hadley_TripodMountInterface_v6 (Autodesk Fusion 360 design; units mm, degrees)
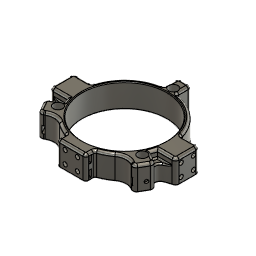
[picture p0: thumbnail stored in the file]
base_mesh_feature "Base Mesh Feature1"
base_mesh_feature "Base Mesh Feature2"
modify "Modify1"
sketch "Sketch2" plane through (0, 0, 0) normal (0, 1, 0) x axis (1, 0, 0)
  line L1 (-90, -12) -> (-90, 12)
  line L2 (90, 12) -> (90, -12)
  line L3 (66.5601, 17) -> (85, 17)
  line L4 (-5, 86.0607) -> (5, 86.0607)
  line L5 (-9, 68.4562) -> (-9, 82.0607)
  line L6 (76.5308, -39.5663) -> (69.8712, -51.101)
  line L7 (61.6032, -52.1011) -> (63.041, -52.9312)
  line L8 (0, 100) -> (0, -90)
  line L9 (-61.5608, -25.1499) -> (-74.7006, -32.7361)
  line L10 (-76.5308, -39.5663) -> (-69.8712, -51.101)
  line L11 (-61.6032, -52.1011) -> (-63.041, -52.9312)
  line L12 (-16.625, -76.125) -> (16.625, -76.125)
  line L13 (85, -17) -> (64.2904, -17)
  line L14 (61.5608, -25.1499) -> (74.7006, -32.7361)
  line L15 (20.625, -56.8758) -> (20.625, -56.875)
  line L16 (20.625, -72.125) -> (20.625, -65.3614)
  line L17 (-20.625, -65.3614) -> (-20.625, -72.125)
  line L18 (-20.625, -56.875) -> (-20.625, -56.8758)
  line L19 (-64.2904, -17) -> (-85, -17)
  line L20 (-85, 17) -> (-66.5601, 17)
  line L21 (9, 82.0607) -> (9, 68.4562)
  curve K1 (74.7006, -32.7361) -> (85, -17)
  curve K2 (81.4412, -18.2716) -> (88.5588, -15.7284)
  curve K3 (-74.7006, -32.7361) -> (-85, -17)
  curve K4 (77.6528, -34.2592) -> (71.7485, -31.2131)
  curve K5 (-81.4412, -18.2716) -> (-88.5588, -15.7284)
  curve K6 (-77.6528, -34.2592) -> (-71.7485, -31.2131)
  circle C1 centre (0, 0) radius 60.5
  circle C2 centre (-0.0046, 69.7633) radius 6.7
  circle C3 centre (-60.4144, -34.8856) radius 6.7
  circle C4 centre (60.4191, -34.8776) radius 6.7
  arc A1 centre (0, 0) radius 66.5 clockwise from (64.2904, -17) to (61.5608, -25.1499)
  arc A2 centre (0, 0) radius 66.5 clockwise from (39.6719, -53.3703) to (22.6052, -62.54)
  arc A3 centre (0, 0) radius 66.5 clockwise from (-22.6052, -62.54) to (-39.6719, -53.3703)
  arc A4 centre (0, 0) radius 66.5 clockwise from (-61.5608, -25.1499) to (-64.2904, -17)
  arc A5 centre (0, 0) radius 66.5 clockwise from (-63.687, 19.1367) to (-11.482, 65.5012)
  arc A6 centre (0, 0) radius 66.5 clockwise from (11.482, 65.5012) to (63.687, 19.1367)
  arc A7 centre (51.6032, -69.4216) radius 20 clockwise from (39.6719, -53.3703) to (61.6032, -52.1011)
  arc A8 centre (-51.6032, -69.4216) radius 20 clockwise from (-61.6032, -52.1011) to (-39.6719, -53.3703)
  arc A9 centre (66.5601, 20) radius 3 clockwise from (66.5601, 17) to (63.687, 19.1367)
  arc A10 centre (12, 68.4562) radius 3 clockwise from (11.482, 65.5012) to (9, 68.4562)
  arc A11 centre (-12, 68.4562) radius 3 clockwise from (-9, 68.4562) to (-11.482, 65.5012)
  arc A12 centre (-66.5601, 20) radius 3 clockwise from (-63.687, 19.1367) to (-66.5601, 17)
  arc A13 centre (23.625, -65.3614) radius 3 clockwise from (20.625, -65.3614) to (22.6052, -62.54)
  arc A14 centre (-23.625, -65.3614) radius 3 clockwise from (-22.6052, -62.54) to (-20.625, -65.3614)
  arc A15 centre (85, 12) radius 5 clockwise from (85, 17) to (90, 12)
  arc A16 centre (85, -12) radius 5 clockwise from (90, -12) to (85, -17)
  arc A17 centre (72.2006, -37.0663) radius 5 clockwise from (74.7006, -32.7361) to (76.5308, -39.5663)
  arc A18 centre (65.541, -48.601) radius 5 clockwise from (69.8712, -51.101) to (63.041, -52.9312)
  arc A19 centre (-65.541, -48.601) radius 5 clockwise from (-63.041, -52.9312) to (-69.8712, -51.101)
  arc A20 centre (-72.2006, -37.0663) radius 5 clockwise from (-76.5308, -39.5663) to (-74.7006, -32.7361)
  arc A21 centre (-85, -12) radius 5 clockwise from (-85, -17) to (-90, -12)
  arc A22 centre (-85, 12) radius 5 clockwise from (-90, 12) to (-85, 17)
  arc A23 centre (16.625, -72.125) radius 4 clockwise from (20.625, -72.125) to (16.625, -76.125)
  arc A24 centre (-16.625, -72.125) radius 4 clockwise from (-16.625, -76.125) to (-20.625, -72.125)
  arc A25 centre (5, 82.0607) radius 4 clockwise from (5, 86.0607) to (9, 82.0607)
  arc A26 centre (-5, 82.0607) radius 4 clockwise from (-9, 82.0607) to (-5, 86.0607)
  point P1 (0, 0)
  point P2 (0, 0)
  point P3 (0, 0)
  point P18 (20.625, -56.8758)
  point P19 (-20.625, -56.8758)
  point P23 (-64.2904, -17)
  point P4 (-90, -17)
  point P5 (-90, 17)
  point P54 (85, -17)
  point P57 (74.7006, -32.7361)
  point P85 (-85, -17)
  point P89 (-74.7006, -32.7361)
  point P80 (79, -19)
  point P86 (-79, -19)
  point P81 (73, -22)
  point P87 (-73, -22)
  point P82 (71, -28)
  point P88 (-71, -28)
  point P83 (88.5588, -15.7284)
  point P92 (-88.5588, -15.7284)
  point P84 (81.4412, -18.2716)
  point P93 (-81.4412, -18.2716)
  point P90 (71.7485, -31.2131)
  point P94 (-71.7485, -31.2131)
  point P91 (77.6528, -34.2592)
  point P95 (-77.6528, -34.2592)
  point P7 (9, 86.0607)
  point P8 (-9, 86.0607)
  coincident P1 P2
  coincident P1 P3
  horizontal L19
  vertical L1
  vertical L2
  horizontal L3
  horizontal L4
  vertical L5
  parallel L5 L8
  parallel L15 L17
  concentric A1 A6
  coincident C1 P18
  collinear L15 L16
  coincident C1 P19
  collinear L17 L18
  concentric A2 A6
  concentric A3 A6
  coincident P23 A6
  concentric A4 A6
  concentric A5 A6
  tangent L7 A7
  tangent A2 A7
  tangent L11 A8
  tangent A3 A8
  tangent L3 A9
  tangent A6 A9
  tangent A6 A10
  tangent L21 A10
  tangent L5 A11
  tangent A5 A11
  tangent A5 A12
  tangent L20 A12
  tangent L16 A13
  tangent A2 A13
  tangent L17 A14
  tangent A3 A14
  equal A13 A14
  tangent L2 A15
  tangent L3 A15
  tangent L2 A16
  tangent L13 A16
  equal A15 A16
  tangent L6 A17
  tangent L14 A17
  equal A15 A17
  tangent L6 A18
  tangent L7 A18
  equal A15 A18
  tangent L10 A19
  tangent L11 A19
  equal A15 A19
  tangent L9 A20
  tangent L10 A20
  equal A15 A20
  coincident P4 L1
  coincident P4 L19
  tangent L1 A21
  tangent L19 A21
  equal A15 A21
  coincident P5 L1
  coincident P5 L20
  tangent L1 A22
  tangent L20 A22
  equal A15 A22
  tangent L12 A23
  tangent L16 A23
  tangent L12 A24
  tangent L17 A24
  equal A23 A24
  midpoint P54 K2
  midpoint P57 K4
  symmetric L8 P54 P85
  symmetric L8 P57 P89
  symmetric L8 P80 P86
  symmetric L8 P81 P87
  symmetric L8 P82 P88
  symmetric L8 P83 P92
  symmetric L8 P84 P93
  symmetric L8 P90 P94
  symmetric L8 P91 P95
  coincident P7 L4
  coincident P7 L21
  tangent L4 A25
  tangent L21 A25
  coincident P8 L4
  coincident P8 L5
  tangent L4 A26
  tangent L5 A26
  equal A25 A26
  dimension "d1" distance P4 P5 = 34
  dimension "d3" distance P1 L2 = 90
  dimension "d4" distance P1 L1 = 90
  dimension "d5" diameter C2 = 13.4
  dimension "d6" distance P7 P8 = 18
  dimension "d7" diameter C1 = 121
  dimension "d8" diameter A1 = 133
  dimension "d21" radius A7 = 20
  dimension "d22" radius A8 = 20
  dimension "d23" radius A9 = 3
  dimension "d24" radius A10 = 3
  dimension "d25" radius A11 = 3
  dimension "d26" radius A12 = 3
  dimension "d27" radius A13 = 3
  dimension "d28" radius A15 = 5
  dimension "d29" radius A23 = 4
  dimension "d32" radius A25 = 4
extrude "Extrude2" new body sketch "Sketch2" profile of C1 A6 L19 L20 L1 L13 L2 L3 C2 L4 L5 L21 C3 C4 L14 L6 L7 L8 L9 L10 L11 L16 L12 L18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 distance 17
fillet "Fillet1" radius 3.5
extrude "Extrude3" cut sketch "Sketch2" profile of C2 C3 C4 L8 no distance stored
extrude "Extrude4" add sketch "Sketch2" profile of A6 L19 L13 L14 L9 K1 K3 to an object
extrude "Extrude5" add sketch "Sketch2" profile of A6 L19 L13 L14 L9 K1 K3 along normal blind 6
fillet "Fillet2" radius 2
sketch "Sketch3" plane through (0, 0, 76.125) normal (0, 0, 1) x axis (1, 0, 0)
  line L1 (16.625, 13.5) -> (16.625, -17)
  line L2 (-16.625, 13.5) -> (16.625, 13.5)
  line L3 (-16.625, -17) -> (-16.625, 13.5)
  line L4 (16.625, -17) -> (-16.625, -17)
  circle C1 centre (8.7189, 8.734) radius 3
  circle C2 centre (8.7189, -8.943) radius 3
  circle C3 centre (-8.9581, 8.734) radius 3
  circle C4 centre (-8.9581, -8.943) radius 3
  dimension "d51" diameter C4 = 6
  dimension "d49" R-Pattern1-uDistance = 17.677
  dimension "d50" R-Pattern1-vDistance = 17.677
extrude "Extrude6" cut sketch "Sketch3" profile of C1 C2 C3 C4 against normal blind 12.9668
sketch "Sketch4" plane through (20.625, 0, 0) normal (1, 0, 0) x axis (0, 0, -1)
  line L1 (-65.3614, 13.5) -> (-65.3614, -17)
  line L2 (-72.125, 13.5) -> (-65.3614, 13.5)
  line L3 (-72.125, -17) -> (-72.125, 13.5)
  line L4 (-68.1057, 13.8389) -> (-71.6057, 13.8389)
  line L5 (-68.1057, 3.8389) -> (-68.1057, 13.8389)
  line L6 (-71.6057, 3.8389) -> (-68.1057, 3.8389)
  line L7 (-71.6057, 13.8389) -> (-71.6057, 3.8389)
  line L8 (-68.1057, -13.8394) -> (-68.1057, -3.8394)
  line L9 (-71.6057, -13.8394) -> (-68.1057, -13.8394)
  line L10 (-71.6057, -3.8394) -> (-71.6057, -13.8394)
  line L11 (-68.1057, -3.8394) -> (-71.6057, -3.8394)
  line L12 (-65.3614, -17) -> (-72.125, -17)
  point P6 (-71.6057, 13.8389)
  point P7 (-68.1057, 13.8389)
  point P8 (-68.1057, 3.8389)
  point P10 (-68.1057, -3.8394)
  point P12 (-71.6057, -3.8394)
  point P13 (-68.1057, -13.8394)
  horizontal L4
  vertical L5
  horizontal L6
  vertical L7
  horizontal L11
  vertical L8
  horizontal L9
  vertical L10
  dimension "d54" distance P6 P7 = 3.5
  dimension "d55" distance P7 P8 = 10
  dimension "d56" distance P10 P12 = 3.5
  dimension "d57" distance P10 P13 = 10
sketch "Sketch5" plane through (-20.625, 0, 0) normal (-1, 0, 0) x axis (0, 0, 1)
  line L1 (72.125, 13.5) -> (72.125, -17)
  line L2 (65.3614, 13.5) -> (72.125, 13.5)
  line L3 (65.3614, -17) -> (65.3614, 13.5)
  line L4 (71.6, 3.8389) -> (71.6, 13.8389)
  line L5 (68.1, -13.8394) -> (71.6, -13.8394)
  line L6 (68.1, -3.8394) -> (68.1, -13.8394)
  line L7 (71.6, -3.8394) -> (68.1, -3.8394)
  line L8 (71.6, 13.8389) -> (68.1, 13.8389)
  line L9 (68.1, 3.8389) -> (71.6, 3.8389)
  line L10 (71.6, -13.8394) -> (71.6, -3.8394)
  line L11 (68.1, 13.8389) -> (68.1, 3.8389)
  line L12 (72.125, -17) -> (65.3614, -17)
  point P6 (71.6, 13.8389)
  point P8 (68.1, 13.8389)
  point P9 (71.6, 3.8389)
  point P11 (68.1, -3.8394)
  point P13 (71.6, -3.8394)
  point P12 (71.6, -13.8394)
  horizontal L8
  vertical L4
  horizontal L9
  vertical L11
  horizontal L7
  vertical L10
  horizontal L5
  vertical L6
  dimension "d58" distance P6 P8 = 3.5
  dimension "d59" distance P6 P9 = 10
  dimension "d60" distance P11 P13 = 3.5
  dimension "d61" distance P12 P13 = 10
extrude "Extrude7" cut sketch "Sketch4" profile of L2 L4 L5 L6 L7 L8 L9 L10 L11 against normal blind 18
extrude "Extrude8" cut sketch "Sketch5" profile of L2 L4 L5 L6 L7 L8 L9 L10 L11 against normal blind 18
sketch "Sketch6" plane through (90, 0, 0) normal (1, 0, 0) x axis (0, 0, -1)
  line L1 (12, 13.5) -> (12, -17)
  line L2 (-12, 13.5) -> (12, 13.5)
  line L3 (-12, -17) -> (-12, 13.5)
  line L4 (12, -17) -> (-12, -17)
  circle C1 centre (8.845, 8.845) radius 3
  circle C2 centre (-8.845, 8.845) radius 3
  circle C3 centre (-8.845, -8.845) radius 3
  circle C4 centre (8.845, -8.845) radius 3
  point P1 (0, 0)
  point P7 (-8.845, 8.845)
  point P6 (8.845, 8.845)
  point P9 (-8.845, -8.845)
  dimension "d70" diameter C2 = 6
  dimension "d71" distance P1 P7 = 8.845
  dimension "d72" distance P1 P6 = 8.845
  dimension "d73" distance P1 P7 = 8.845
  dimension "d74" distance P1 P9 = 8.845
  dimension "d68" R-Pattern1-uDistance = 17.69
  dimension "d69" R-Pattern1-vDistance = -17.69
sketch "Sketch7" plane through (-90, 0, 0) normal (-1, 0, 0) x axis (0, 0, 1)
  line L1 (12, 13.5) -> (12, -17)
  line L2 (-12, 13.5) -> (12, 13.5)
  line L3 (-12, -17) -> (-12, 13.5)
  line L4 (12, -17) -> (-12, -17)
  circle C1 centre (8.845, 8.845) radius 3
  circle C2 centre (-8.845, 8.845) radius 3
  circle C3 centre (-8.845, -8.845) radius 3
  circle C4 centre (8.845, -8.845) radius 3
  point P1 (0, 0)
  point P7 (-8.845, 8.845)
  dimension "d79" diameter C2 = 6
  dimension "d80" distance P1 P7 = 8.845
  dimension "d81" distance P1 P7 = 8.845
  dimension "d77" R-Pattern1-uDistance = 17.69
  dimension "d78" R-Pattern1-vDistance = -17.69
chamfer "Chamfer4" distance 1
extrude "Extrude9" cut sketch "Sketch6" profile of C1 C2 C3 C4 against normal blind 14
extrude "Extrude10" cut sketch "Sketch7" profile of C1 C2 C3 C4 against normal blind 14
sketch "Sketch8" plane through (0, 0, -17) normal (0, 0, -1) x axis (-1, 0, 0)
  line L1 (85, -16) -> (66.5601, -16)
  line L2 (85, 13.5) -> (85, -16)
  line L3 (66.5601, 13.5) -> (85, 13.5)
  line L4 (66.5601, -16) -> (66.5601, 13.5)
  line L5 (83.9928, -13.8394) -> (83.9928, -3.8394)
  line L6 (80.4928, -13.8394) -> (83.9928, -13.8394)
  line L7 (80.4928, -3.8394) -> (80.4928, -13.8394)
  line L8 (83.9928, -3.8394) -> (80.4928, -3.8394)
  line L9 (83.9928, 13.8389) -> (80.4928, 13.8389)
  line L10 (83.9928, 3.8389) -> (83.9928, 13.8389)
  line L11 (80.4928, 13.8389) -> (80.4928, 3.8389)
  line L12 (80.4928, 3.8389) -> (83.9928, 3.8389)
  point P7 (80.4928, 13.8389)
  point P8 (83.9928, 13.8389)
  point P6 (83.9928, 3.8389)
  point P10 (83.9928, -3.8394)
  point P12 (80.4928, -3.8394)
  point P13 (83.9928, -13.8394)
  horizontal L9
  vertical L10
  horizontal L12
  vertical L11
  horizontal L8
  vertical L5
  horizontal L6
  vertical L7
  dimension "d87" distance P7 P8 = 3.5
  dimension "d88" distance P6 P8 = 10
  dimension "d89" distance P10 P12 = 3.5
  dimension "d90" distance P10 P13 = 10
sketch "Sketch9" plane through (0, 0, -17) normal (0, 0, -1) x axis (-1, 0, 0)
  line L1 (-66.5601, -16) -> (-85, -16)
  line L2 (-66.5601, 13.5) -> (-66.5601, -16)
  line L3 (-85, 13.5) -> (-66.5601, 13.5)
  line L4 (-85, -16) -> (-85, 13.5)
  line L5 (-80.5629, -13.8394) -> (-80.5629, -3.8394)
  line L6 (-84.0629, -13.8394) -> (-80.5629, -13.8394)
  line L7 (-84.0629, -3.8394) -> (-84.0629, -13.8394)
  line L8 (-80.5629, -3.8394) -> (-84.0629, -3.8394)
  line L9 (-80.5629, 13.8389) -> (-84.0629, 13.8389)
  line L10 (-80.5629, 3.8389) -> (-80.5629, 13.8389)
  line L11 (-84.0629, 13.8389) -> (-84.0629, 3.8389)
  line L12 (-84.0629, 3.8389) -> (-80.5629, 3.8389)
  point P7 (-84.0629, 13.8389)
  point P8 (-80.5629, 13.8389)
  point P6 (-80.5629, 3.8389)
  point P10 (-80.5629, -3.8394)
  point P12 (-84.0629, -3.8394)
  point P13 (-80.5629, -13.8394)
  horizontal L9
  vertical L10
  horizontal L12
  vertical L11
  horizontal L8
  vertical L5
  horizontal L6
  vertical L7
  dimension "d93" distance P7 P8 = 3.5
  dimension "d94" distance P6 P8 = 10
  dimension "d95" distance P10 P12 = 3.5
  dimension "d96" distance P10 P13 = 10
extrude "Extrude12" cut sketch "Sketch8" + "Sketch9" profile of S1:L3 S1:L5 S1:L6 S1:L7 S1:L8 S1:L9 S1:L10 S1:L11 S1:L12 S2:L3 S2:L5 S2:L6 S2:L7 S2:L8 S2:L9 S2:L10 S2:L11 S2:L12 blind -31.564
sketch "Sketch10" plane through (0, 0, -86.0607) normal (0, 0, -1) x axis (-1, 0, 0)
  line L1 (5, -16) -> (-5, -16)
  line L2 (5, 13.5) -> (5, -16)
  line L3 (-5, 13.5) -> (5, 13.5)
  line L4 (-5, -16) -> (-5, 13.5)
  circle C1 centre (0, -5) radius 2.5
  dimension "d99" diameter C1 = 5
sketch "Sketch11" plane through (-74.5308, 0, 43.0304) normal (-0.866, 0, 0.5) x axis (0.5, 0, 0.866)
  line L1 (9.3192, -16) -> (-4, -16)
  line L2 (9.3192, 13.5) -> (9.3192, -16)
  line L3 (-4, 13.5) -> (9.3192, 13.5)
  line L4 (-4, -16) -> (-4, 13.5)
  circle C1 centre (0, -5) radius 2.5
  dimension "d100" diameter C1 = 5
sketch "Sketch12" plane through (74.5308, 0, 43.0304) normal (0.866, 0, 0.5) x axis (0.5, 0, -0.866)
  line L1 (4, -16) -> (-9.3192, -16)
  line L2 (4, 13.5) -> (4, -16)
  line L3 (-9.3192, 13.5) -> (4, 13.5)
  line L4 (-9.3192, -16) -> (-9.3192, 13.5)
  circle C1 centre (0, -5) radius 2.5
  dimension "d101" diameter C1 = 5
extrude "Extrude13" cut sketch "Sketch12" profile of C1 against normal blind 15
extrude "Extrude14" cut sketch "Sketch10" profile of C1 against normal blind 15
extrude "Extrude15" cut sketch "Sketch11" profile of C1 against normal blind 15
work_plane "WorkPlane1" RotateAngle -30
work_plane "WorkPlane2" AlongDistance 10.765
work_plane "WorkPlane3" RotateAngle -90
work_plane "WorkPlane4" AlongDistance 35.843
sketch "Sketch15" plane through (49.8242, 13.5, 59.7616) normal (-0.5, 0, 0.866) x axis (-0.866, 0, -0.5)
sketch "Sketch16" plane through (49.8242, 13.5, 59.7616) normal (-0.5, 0, 0.866) x axis (-0.866, 0, -0.5)
  line L1 (-9.9411, 13.4852) -> (-6.4411, 13.4852)
  line L2 (-9.9411, 23.4852) -> (-9.9411, 13.4852)
  line L3 (-6.4411, 23.4852) -> (-9.9411, 23.4852)
  line L4 (-6.4411, 13.4852) -> (-6.4411, 23.4852)
  point P2 (-9.9411, 23.4852)
  point P3 (-6.4411, 23.4852)
  point P5 (-6.4411, 13.4852)
  horizontal L3
  vertical L4
  horizontal L1
  vertical L2
  dimension "d112" distance P2 P3 = 3.5
  dimension "d113" distance P3 P5 = 10
extrude "Extrude16" cut sketch "Sketch16" against normal blind 32.826
work_plane "WorkPlane5" RotateAngle -90
work_plane "WorkPlane6" AlongDistance 29.579
sketch "Sketch17" plane through (-52.9562, 13.5, 54.3369) normal (0.5, 0, 0.866) x axis (-0.866, 0, 0.5)
  line L1 (6.4066, 13.4737) -> (9.9066, 13.4737)
  line L2 (6.4066, 23.4737) -> (6.4066, 13.4737)
  line L3 (9.9066, 23.4737) -> (6.4066, 23.4737)
  line L4 (9.9066, 13.4737) -> (9.9066, 23.4737)
  point P2 (6.4066, 23.4737)
  point P3 (9.9066, 23.4737)
  point P5 (9.9066, 13.4737)
  horizontal L3
  vertical L4
  horizontal L1
  vertical L2
  dimension "d118" distance P2 P3 = 3.5
  dimension "d119" distance P3 P5 = 10
extrude "Extrude17" cut sketch "Sketch17" against normal blind 26.146
sketch "Sketch18" plane through (-9, 0, 0) normal (-1, 0, 0) x axis (0, 0, 1)
  line L1 (-68.4562, -16) -> (-82.0607, -16)
  line L2 (-68.4562, 13.5) -> (-68.4562, -16)
  line L3 (-82.0607, 13.5) -> (-68.4562, 13.5)
  line L4 (-82.0607, -16) -> (-82.0607, 13.5)
  line L5 (-83.0393, -9.9804) -> (-79.5393, -9.9804)
  line L6 (-83.0393, 0.0196) -> (-83.0393, -9.9804)
  line L7 (-79.5393, 0.0196) -> (-83.0393, 0.0196)
  line L8 (-79.5393, -9.9804) -> (-79.5393, 0.0196)
  point P6 (-83.0393, 0.0196)
  point P7 (-79.5393, 0.0196)
  point P9 (-79.5393, -9.9804)
  horizontal L7
  vertical L8
  horizontal L5
  vertical L6
  dimension "d122" distance P6 P7 = 3.5
  dimension "d123" distance P7 P9 = 10
extrude "Extrude18" cut sketch "Sketch18" profile of L4 L5 L6 L7 L8 against normal blind 14.498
